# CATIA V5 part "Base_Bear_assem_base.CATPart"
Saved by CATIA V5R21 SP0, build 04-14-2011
Part number: Base_Bear_assem_base
Bounding box of the stored display mesh (mm): x -49.234 to 49.234, y -29.276 to 56, z -1.5 to 10
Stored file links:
  F:\教程\Robotic_Arm_Arduino_Kinect\机械臂CAD\Arm_Detailed_Design\Base_Bear_assem_base.CATPart
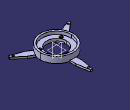
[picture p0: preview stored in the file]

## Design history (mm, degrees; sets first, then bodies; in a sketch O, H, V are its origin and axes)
Body1 (main body)
  Sketch1 on xy-plane, origin (0, 0, 0), H (1, 0, 0), V (0, 1, 0)
    circle A1 centre (0, 0) radius 26.5
    radius A1 = 26.5
  Pad1: profile Sketch1, direction (0, 0, 1), length 10
  Sketch2 on end face of Pad1, origin (0, 0, 10), H (1, 0, 0), V (0, 1, 0)
    circle A1 centre (0, 0) radius 23.5
    radius A1 = 23.5
  Pocket1: profile Sketch2, direction (0, 0, -1), up to start face of Pad1, offset -5
  Sketch3 on end face of Pocket1, origin (0, 0, 5), H (1, 0, 0), V (0, 1, 0)
    circle A1 centre (0, 0) radius 16
    radius A1 = 16
  Pocket2: profile Sketch3, direction (0, 0, -1), through (limit type 3)
  Sketch4 on end face of Pocket1, origin (0, 0, 5), H (1, 0, 0), V (0, 1, 0)
    circle A1 centre (0, 19.5) radius 2.5
    point P1 (0, 19.5)
    circle A2 centre (-16.8875, -9.75) radius 2.5
    circle A3 centre (16.8875, -9.75) radius 2.5
    radius A1 = 2.5
    distance P1 H = 19.5
    coincidence: P1 V
  Pocket3: profile Sketch4, direction (0, 0, -1), length 1.5
  Sketch5 on end face of Pocket3, origin (0, 0, 3.5), H (1, 0, 0), V (0, 1, 0)
    circle A1 centre (0, 19.5) radius 1.5
    point P1 (0, 19.5)
    circle A2 centre (-16.8875, -9.75) radius 1.5
    circle A3 centre (16.8875, -9.75) radius 1.5
    radius A1 = 1.5
    distance P1 H = 19.5
    coincidence: P1 V
  Pocket4: profile Sketch5, direction (0, 0, -1), through (limit type 3)
  Sketch6 on start face of Pad1, origin (0, 0, 0), H (1, 0, 0), V (0, -1, 0)
    line L1 (-5, -13.8154) -> (5, -13.8154)
    line L2 (5, -13.8154) -> (5, -28.4504)
    line L3 (5, -28.4504) -> (-5, -28.4504)
    line L4 (-5, -28.4504) -> (-5, -13.8154)
    line L5 (22.1387, 18.5553) -> (27.1387, 9.8951)
    line L6 (9.4645, 11.2378) -> (22.1387, 18.5553)
    line L7 (27.1387, 9.8951) -> (14.4645, 2.5776)
    line L8 (14.4645, 2.5776) -> (9.4645, 11.2378)
    line L9 (-27.1387, 9.8951) -> (-22.1387, 18.5553)
    line L10 (-14.4645, 2.5776) -> (-27.1387, 9.8951)
    line L11 (-22.1387, 18.5553) -> (-9.4645, 11.2378)
    line L12 (-9.4645, 11.2378) -> (-14.4645, 2.5776)
    distance L2 V = 5
    distance V L4 = 5
    horizontal: L1 H, L3 H
    vertical: L2 V, L4 V
  Pocket5: profile Sketch6, direction (0, 0, 1), length 1.5
Body2
  Sketch7 on end face of Pocket5, origin (0, 0, 1.5), H (1, 0, 0), V (0, -1, 0)
    line L1 (-5, -16) -> (5, -16)
    line L2 (5, -16) -> (5, -36)
    point P2 (5, -36)
    line L3 (5, -36) -> (1.4735, -56)
    line L4 (1.4735, -56) -> (-1.4735, -56)
    line L5 (-1.4735, -56) -> (-5, -36)
    point P5 (-5, -36)
    line L6 (-5, -36) -> (-5, -16)
    reference projected line E1 (-5, -13.8154) -> (-5, -28.4504) from edge [end face of Pocket5 | face of Pocket5 from Sketch6.L4]
    reference projected line E2 (5, -28.4504) -> (5, -13.8154) from edge [end face of Pocket5 | face of Pocket5 from Sketch6.L2]
    reference projected arc E3 centre (0, 0) radius 16 from (-10.6624, 11.9295) to (-15.6624, 3.2692) ccw from edge [end face of Pocket5 | face of Pocket2 from Sketch3.A1]
    circle A1 centre (0, -51) radius 1.5
    point P7 (0, -51)
    circle A2 centre (0, -19.5) radius 1.5
    point P8 (0, -19.5)
    reference projected circle E6 centre (0, -19.5) radius 1.5 from edge [end face of Pocket5 | face of Pocket4 from Sketch5.A1]
    angle L5 L6 = 170
    angle L3 L2 = 170
    distance L1 L4 = 40
    distance P2 L1 = 20
    distance P5 L1 = 20
    radius A1 = 1.5
    distance P7 L4 = 5
    horizontal: L1 H, L4 H
    vertical: L2 V, L6 V
    coincidence: L6 E1, L2 E2, P7 V, P8 V, A2 E6
    tangency: L1 E3
  Pad2: profile Sketch7, direction (0, 0, -1), length 3
  CircPattern1: of Pad2, instances 3, angular step 120, axis from Z axis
